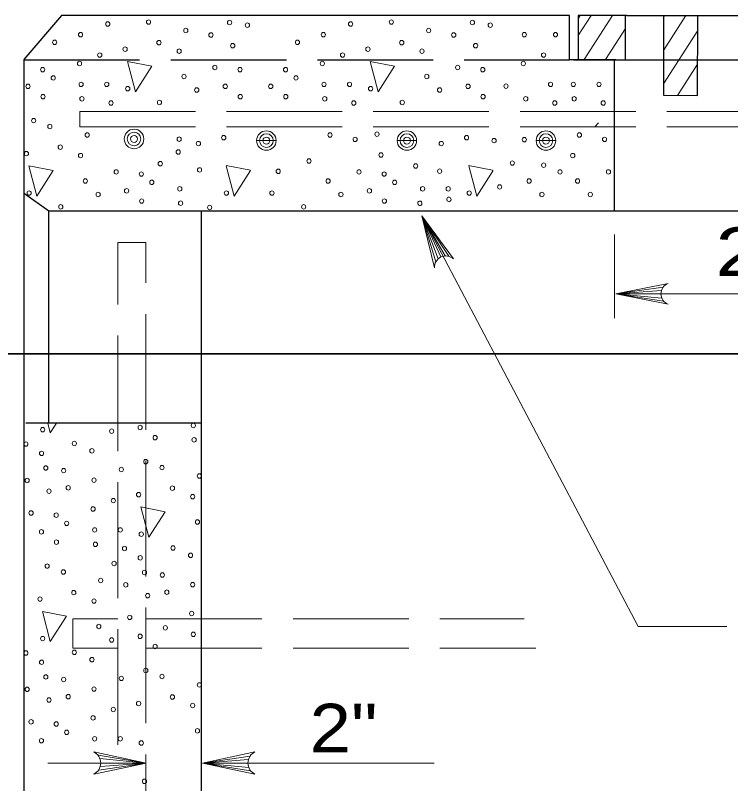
# Model space of a CAD drawing. Extents: x 1329.9 to 1363.9, y 715.5 to 737.5.
# Drawn here: x 1332.839 to 1335.139, y 731.635 to 734.106 of the extents above; entities that cross this region are included whole.
import ezdxf
from ezdxf.enums import TextEntityAlignment as Align

# ---------------------------------------------------------------- set-up
doc = ezdxf.new("R2010")
doc.units = 0
doc.header["$LTSCALE"] = 0.062
doc.linetypes.add('LONG_DASHED', pattern=[7.5, 6, -1.5])
doc.layers.add('1', color=7, linetype='Continuous', lineweight=13)

msp = doc.modelspace()

# ---------------------------------------------------------------- linework, layer by layer
at = {"layer": '1'}
for p, q in [((1334.64908, 734.04133), (1334.6905, 734.10575)), ((1334.64908, 734.095), (1334.656, 734.10575)), ((1334.66808, 733.96333), (1334.75958, 734.10575)), ((1334.9235, 733.99275), (1334.99592, 734.1055)), ((1334.92358, 734.10033), (1334.92708, 734.10567)), ((1335.03358, 734.10533), (1334.92367, 734.10575)), ((1334.73708, 733.96333), (1334.80158, 734.06383)), ((1334.92342, 733.88508), (1335.0335, 734.05658)), ((1334.96892, 733.84858), (1335.03333, 733.94892)), ((1333.04633, 733.79608), (1333.04633, 733.74733)), ((1333.04633, 733.79608), (1333.106, 733.79608)), ((1333.04633, 733.74733), (1333.108, 733.74733)), ((1334.70242, 733.74733), (1334.71467, 733.76033)), ((1332.88267, 733.62175), (1332.90833, 733.52442)), ((1333.595, 733.60817), (1333.51708, 733.62333)), ((1334.37408, 733.60817), (1334.29617, 733.62333)), ((1334.208, 733.32883), (1334.14617, 733.46058)), ((1334.2215, 733.33217), (1334.14617, 733.46058)), ((1334.23292, 733.33108), (1334.14617, 733.46058)), ((1334.19892, 733.32283), (1334.14617, 733.46058)), ((1334.19158, 733.31367), (1334.14617, 733.46058)), ((1334.76558, 733.40058), (1334.76558, 733.13242)), ((1334.92225, 733.2315), (1334.76992, 733.21025)), ((1334.91708, 733.221), (1334.76992, 733.21025)), ((1334.86892, 733.21025), (1334.76992, 733.21025)), ((1334.9155, 733.21025), (1334.76992, 733.21025)), ((1334.91817, 733.19658), (1334.76992, 733.21025)), ((1334.924, 733.18667), (1334.76992, 733.21025)), ((1333.1055, 731.7265), (1333.25958, 731.7015)), ((1333.11133, 731.716), (1333.25958, 731.7015)), ((1333.59392, 731.72408), (1333.44167, 731.7015)), ((1332.94333, 731.7015), (1333.25958, 731.7015)), ((1333.10733, 731.679), (1333.25958, 731.7015)), ((1333.11242, 731.69017), (1333.25958, 731.7015)), ((1333.114, 731.7015), (1333.25958, 731.7015)), ((1333.58875, 731.71292), (1333.44167, 731.7015)), ((1333.44167, 731.7015), (1334.18592, 731.7015)), ((1333.58725, 731.7015), (1333.44167, 731.7015)), ((1333.58992, 731.68708), (1333.44167, 731.7015)), ((1333.59575, 731.67658), (1333.44167, 731.7015))]:
    msp.add_line(p, q, dxfattribs=at)
at = {"layer": '1', "lineweight": 25}
for p, q in [((1334.80158, 733.96325), (1334.80158, 734.10575)), ((1334.80542, 734.10575), (1336.53992, 734.10575)), ((1332.86692, 733.96325), (1332.86692, 733.5425)), ((1334.76558, 733.47708), (1334.76558, 733.96325)), ((1334.80125, 733.96325), (1336.54408, 733.96325)), ((1332.86692, 733.5425), (1332.86692, 732.80092)), ((1332.86858, 733.53275), (1332.94725, 733.47708)), ((1332.94725, 732.79425), (1332.94725, 733.47708)), ((1332.94725, 733.47708), (1334.76992, 733.47708)), ((1333.43842, 729.84383), (1333.43842, 733.47708)), ((1334.76992, 733.47708), (1336.57183, 733.47708)), ((1332.86692, 732.80092), (1332.86692, 729.46942)), ((1333.43842, 732.79425), (1332.87258, 732.79425))]:
    msp.add_line(p, q, dxfattribs=at)
at = {"layer": '1', "linetype": 'LONG_DASHED', "lineweight": 25}
msp.add_line((1332.86692, 733.96325), (1334.62167, 733.96325), dxfattribs=at)
at = {"layer": '1', "linetype": 'LONG_DASHED'}
for p, q in [((1333.04633, 733.79608), (1338.30508, 733.79608)), ((1333.04633, 733.74733), (1338.30508, 733.74733)), ((1333.61533, 733.70317), (1333.678, 733.70317)), ((1334.06717, 733.70317), (1334.12975, 733.70317)), ((1334.06717, 733.70317), (1334.12975, 733.70317)), ((1334.51433, 733.70317), (1334.57692, 733.70317)), ((1334.51433, 733.70317), (1334.57692, 733.70317)), ((1334.51433, 733.70317), (1334.57692, 733.70317)), ((1333.16925, 733.37567), (1333.259, 733.37567)), ((1333.16925, 731.76017), (1333.16925, 733.37567)), ((1333.02425, 732.1655), (1333.02425, 732.07058)), ((1333.02425, 732.1655), (1333.16917, 732.1655)), ((1333.26033, 732.1655), (1334.47525, 732.1655)), ((1333.02425, 732.07058), (1333.16917, 732.07058)), ((1333.26033, 732.07058), (1334.51267, 732.07058))]:
    msp.add_line(p, q, dxfattribs=at)
at = {"layer": '1', "lineweight": 25}
for points in [[(1334.76992, 733.96325), (1334.62167, 733.96325), (1334.62167, 734.10575), (1332.98725, 734.10575), (1332.8665, 733.96333)], [(1334.80542, 734.10575), (1334.64908, 734.10575), (1334.64908, 733.96325)], [(1334.92367, 734.10575), (1334.92325, 733.84867), (1335.03325, 733.84825), (1335.03358, 734.10533)], [(1334.63383, 733.96325), (1334.76992, 733.96325), (1334.80125, 733.96325)]]:
    msp.add_lwpolyline(points, dxfattribs=at)
at = {"layer": '1'}
for points in [[(1333.19992, 733.9575), (1333.22558, 733.86025), (1333.27775, 733.94242)], [(1333.98075, 733.9575), (1334.00642, 733.86025), (1334.05858, 733.94242)], [(1333.24333, 732.525), (1333.269, 732.42758), (1333.32117, 732.50975)], [(1332.92617, 732.18917), (1332.95175, 732.09183), (1333.00408, 732.174)]]:
    msp.add_lwpolyline(points, close=True, dxfattribs=at)
for points in [[(1332.90833, 733.52442), (1332.96058, 733.6065), (1332.88267, 733.62175)], [(1333.51708, 733.62175), (1333.54275, 733.52442), (1333.595, 733.6065)], [(1334.29792, 733.62175), (1334.3235, 733.52442), (1334.37583, 733.6065)], [(1334.14617, 733.46058), (1334.84225, 732.14025), (1335.12683, 732.14025)], [(1334.24808, 733.32258), (1334.14617, 733.46058), (1334.18717, 733.294)], [(1334.93817, 733.17658), (1334.76992, 733.21025), (1334.93817, 733.24383)], [(1334.76992, 733.21025), (1335.88917, 733.21025), (1336.57183, 733.21025)], [(1332.94375, 732.79417), (1332.95175, 732.7635), (1332.97142, 732.79417)], [(1333.09133, 731.73717), (1333.25958, 731.7015), (1333.09133, 731.66592)], [(1333.60983, 731.66592), (1333.44167, 731.7015), (1333.60983, 731.73717)]]:
    msp.add_lwpolyline(points, dxfattribs=at)
at = {"layer": '1', "linetype": 'LONG_DASHED'}
msp.add_lwpolyline([(1333.259, 729.40917), (1333.259, 729.46942), (1333.259, 733.37567)], dxfattribs=at)
at = {"layer": '1', "lineweight": 35}
msp.add_lwpolyline([(1332.47342, 733.01742), (1338.878, 733.01742), (1338.878, 732.60617)], dxfattribs=at)
at = {"layer": '1'}
for centre, radius in [((1333.22102, 733.70835), 0.03133), ((1333.22102, 733.70835), 0.0219), ((1333.22102, 733.70835), 0.01122), ((1333.64666, 733.70316), 0.03133), ((1333.64666, 733.70316), 0.0219), ((1333.64666, 733.70316), 0.01122), ((1334.09846, 733.70316), 0.03133), ((1334.09846, 733.70316), 0.0219), ((1334.09846, 733.70316), 0.01122), ((1334.54563, 733.70316), 0.03133), ((1334.54563, 733.70316), 0.0219), ((1334.54563, 733.70316), 0.01122)]:
    msp.add_circle(centre, radius, dxfattribs=at)
for centre, start, end in [((1334.22336, 733.29598), 47.22812, 183.05425), ((1334.95175, 733.21026), 112.08782, 247.91395)]:
    msp.add_arc(centre, 0.03631, start, end, dxfattribs=at)
for centre, major_axis in [((1333.13658, 734.07782), (0, 0.00718)), ((1333.26763, 734.08415), (0, 0.00718)), ((1333.52832, 734.08263), (0, 0.00718)), ((1333.91738, 734.07782), (0, 0.00718)), ((1334.04844, 734.08415), (0, 0.00718)), ((1334.30912, 734.08263), (0, 0.00718)), ((1333.38753, 734.05694), (0, 0.00718)), ((1333.58568, 734.07441), (0, 0.00718)), ((1334.16834, 734.05694), (0, 0.00718)), ((1334.36648, 734.07441), (0, 0.00718)), ((1333.04892, 734.04357), (0, 0.00718)), ((1333.46831, 734.04273), (0, 0.00718)), ((1333.82973, 734.04357), (0, 0.00718)), ((1334.24912, 734.04273), (0, 0.00718)), ((1334.47608, 734.04357), (0, 0.00718)), ((1334.57631, 734.04357), (0, 0.00718)), ((1332.96582, 734.01916), (0, 0.00718)), ((1333.30099, 734.01793), (0, 0.00718)), ((1333.53852, 734.00825), (0, 0.00718)), ((1333.74662, 734.01916), (0, 0.00718)), ((1334.0818, 734.01793), (0, 0.00718)), ((1334.31933, 734.00825), (0, 0.00718)), ((1333.19225, 733.99706), (0, 0.00718)), ((1333.36612, 733.99073), (0, 0.00718)), ((1333.97305, 733.99706), (0, 0.00718)), ((1334.14693, 733.99073), (0, 0.00718)), ((1333.11083, 733.97803), (0, 0.00718)), ((1333.89163, 733.97803), (0, 0.00718)), ((1334.53799, 733.97803), (0, 0.00718)), ((1332.92733, 733.93118), (0, 0.00718)), ((1333.0458, 733.95082), (0, 0.00718)), ((1333.4809, 733.93818), (0, 0.00718)), ((1333.56173, 733.93118), (0, 0.00718)), ((1333.70813, 733.93118), (0, 0.00718)), ((1333.82661, 733.95082), (0, 0.00718)), ((1334.2617, 733.93818), (0, 0.00718)), ((1334.34253, 733.93118), (0, 0.00718)), ((1334.47296, 733.95082), (0, 0.00718)), ((1332.96101, 733.90459), (0, 0.00718)), ((1333.38156, 733.90913), (0, 0.00718)), ((1333.74181, 733.90459), (0, 0.00718)), ((1334.16236, 733.90913), (0, 0.00718)), ((1333.05093, 733.88372), (0, 0.00718)), ((1333.13319, 733.88372), (0, 0.00718)), ((1333.83174, 733.88372), (0, 0.00718)), ((1333.914, 733.88372), (0, 0.00718)), ((1334.56035, 733.88372), (0, 0.00718)), ((1334.63378, 733.88372), (0, 0.00718)), ((1334.71604, 733.88372), (0, 0.00718)), ((1332.87991, 733.87739), (0, 0.00718)), ((1333.20081, 733.87012), (0, 0.00718)), ((1333.42269, 733.86558), (0, 0.00718)), ((1333.51431, 733.87739), (0, 0.00718)), ((1333.66071, 733.87739), (0, 0.00718)), ((1333.98161, 733.87012), (0, 0.00718)), ((1334.20349, 733.86558), (0, 0.00718)), ((1334.29511, 733.87739), (0, 0.00718)), ((1334.41704, 733.87827), (0, 0.00718)), ((1332.92818, 733.84442), (0, 0.00718)), ((1333.05347, 733.83748), (0, 0.00718)), ((1333.56258, 733.84442), (0, 0.00718)), ((1333.70898, 733.84442), (0, 0.00718)), ((1333.83427, 733.83748), (0, 0.00718)), ((1334.34338, 733.84442), (0, 0.00718)), ((1334.48063, 733.83748), (0, 0.00718)), ((1334.63632, 733.83748), (0, 0.00718)), ((1333.14689, 733.82388), (0, 0.00718)), ((1333.30274, 733.82567), (0, 0.00718)), ((1333.92769, 733.82388), (0, 0.00718)), ((1334.08354, 733.82567), (0, 0.00718)), ((1334.57404, 733.82388), (0, 0.00718)), ((1334.72973, 733.82388), (0, 0.00718)), ((1332.8982, 733.76735), (0, 0.00718)), ((1332.95043, 733.74832), (0, 0.00718)), ((1333.07033, 733.72112), (0, 0.00718)), ((1333.36612, 733.70774), (0, 0.00718)), ((1333.50944, 733.71252), (0, 0.00718)), ((1333.85114, 733.72112), (0, 0.00718)), ((1333.93192, 733.70691), (0, 0.00718)), ((1334.00213, 733.72371), (0, 0.00718)), ((1334.29025, 733.71252), (0, 0.00718)), ((1334.65318, 733.72112), (0, 0.00718)), ((1334.73396, 733.70691), (0, 0.00718)), ((1333.42803, 733.69349), (0, 0.00718)), ((1334.20883, 733.69349), (0, 0.00718)), ((1334.37885, 733.70302), (0, 0.00718)), ((1334.47608, 733.70619), (0, 0.00718)), ((1332.87505, 733.66123), (0, 0.00718)), ((1332.98379, 733.68211), (0, 0.00718)), ((1333.363, 733.66629), (0, 0.00718)), ((1333.04892, 733.65491), (0, 0.00718)), ((1333.78359, 733.63728), (0, 0.00718)), ((1334.01511, 733.65685), (0, 0.00718)), ((1334.63177, 733.65491), (0, 0.00718)), ((1333.30523, 733.62885), (0, 0.00718)), ((1333.4316, 733.6088), (0, 0.00718)), ((1334.12672, 733.62141), (0, 0.00718)), ((1334.4374, 733.63082), (0, 0.00718)), ((1334.53833, 733.62404), (0, 0.00718)), ((1333.1637, 733.60235), (0, 0.00718)), ((1333.24453, 733.59536), (0, 0.00718)), ((1333.68465, 733.60433), (0, 0.00718)), ((1333.9445, 733.60235), (0, 0.00718)), ((1334.02533, 733.59536), (0, 0.00718)), ((1334.20393, 733.60481), (0, 0.00718)), ((1334.59085, 733.60235), (0, 0.00718)), ((1334.74654, 733.60235), (0, 0.00718)), ((1333.06436, 733.5733), (0, 0.00718)), ((1333.27821, 733.56877), (0, 0.00718)), ((1333.84517, 733.5733), (0, 0.00718)), ((1334.05901, 733.56877), (0, 0.00718)), ((1334.49152, 733.5733), (0, 0.00718)), ((1334.64721, 733.5733), (0, 0.00718)), ((1332.88361, 733.53429), (0, 0.00718)), ((1333.19711, 733.54157), (0, 0.00718)), ((1333.36813, 733.54789), (0, 0.00718)), ((1333.51801, 733.53429), (0, 0.00718)), ((1333.66441, 733.53429), (0, 0.00718)), ((1333.97791, 733.54157), (0, 0.00718)), ((1334.14894, 733.54789), (0, 0.00718)), ((1334.2312, 733.54789), (0, 0.00718)), ((1334.29881, 733.53429), (0, 0.00718)), ((1334.39679, 733.55411), (0, 0.00718)), ((1333.10549, 733.52976), (0, 0.00718)), ((1333.8863, 733.52976), (0, 0.00718)), ((1334.23351, 733.51418), (-0.00198, 0.0069)), ((1334.53265, 733.52976), (0, 0.00718)), ((1334.68834, 733.52976), (0, 0.00718)), ((1332.98554, 733.48985), (0, 0.00718)), ((1333.24538, 733.5086), (0, 0.00718)), ((1333.37067, 733.50166), (0, 0.00718)), ((1333.46408, 733.48806), (0, 0.00718)), ((1333.76634, 733.48985), (0, 0.00718)), ((1334.02618, 733.5086), (0, 0.00718)), ((1334.13996, 733.50154), (-0.00198, 0.0069)), ((1332.92706, 732.77338), (0, 0.00718)), ((1333.14894, 732.76884), (0, 0.00718)), ((1333.24056, 732.78065), (0, 0.00718)), ((1333.41158, 732.78698), (0, 0.00718)), ((1333.28882, 732.74768), (0, 0.00718)), ((1332.87314, 732.72714), (0, 0.00718)), ((1333.02899, 732.72893), (0, 0.00718)), ((1333.41412, 732.74074), (0, 0.00718)), ((1332.92362, 732.6972), (0, 0.00718)), ((1333.0855, 732.70537), (0, 0.00718)), ((1333.25885, 732.67061), (0, 0.00718)), ((1332.93737, 732.65007), (0, 0.00718)), ((1333.18003, 732.64526), (0, 0.00718)), ((1333.31108, 732.65158), (0, 0.00718)), ((1332.99473, 732.64184), (0, 0.00718)), ((1333.43098, 732.62438), (0, 0.00718)), ((1332.87736, 732.61017), (0, 0.00718)), ((1333.09237, 732.61101), (0, 0.00718)), ((1332.94757, 732.57569), (0, 0.00718)), ((1333.00927, 732.5866), (0, 0.00718)), ((1333.34444, 732.58537), (0, 0.00718)), ((1333.23569, 732.56449), (0, 0.00718)), ((1333.40957, 732.55817), (0, 0.00718)), ((1333.15428, 732.54546), (0, 0.00718)), ((1332.88995, 732.50561), (0, 0.00718)), ((1332.97078, 732.49862), (0, 0.00718)), ((1333.08925, 732.51826), (0, 0.00718)), ((1333.00446, 732.47203), (0, 0.00718)), ((1333.42501, 732.47656), (0, 0.00718)), ((1333.09438, 732.45115), (0, 0.00718)), ((1333.17664, 732.45115), (0, 0.00718)), ((1332.92336, 732.44483), (0, 0.00718)), ((1333.24426, 732.43755), (0, 0.00718)), ((1332.97163, 732.41186), (0, 0.00718)), ((1333.09692, 732.40492), (0, 0.00718)), ((1333.19033, 732.39132), (0, 0.00718)), ((1333.34619, 732.39311), (0, 0.00718)), ((1333.24082, 732.36138), (0, 0.00718)), ((1333.4027, 732.36955), (0, 0.00718)), ((1332.94165, 732.33479), (0, 0.00718)), ((1333.15687, 732.34324), (0, 0.00718)), ((1332.99388, 732.31576), (0, 0.00718)), ((1333.25457, 732.31425), (0, 0.00718)), ((1333.31193, 732.30602), (0, 0.00718)), ((1333.11378, 732.28856), (0, 0.00718)), ((1333.19456, 732.27434), (0, 0.00718)), ((1333.40957, 732.27518), (0, 0.00718)), ((1333.02724, 732.24955), (0, 0.00718)), ((1333.32647, 732.25078), (0, 0.00718)), ((1332.91849, 732.22867), (0, 0.00718)), ((1333.26477, 732.23986), (0, 0.00718)), ((1333.09237, 732.22235), (0, 0.00718)), ((1333.40645, 732.18244), (0, 0.00718)), ((1333.20715, 732.16979), (0, 0.00718)), ((1333.10781, 732.14074), (0, 0.00718)), ((1333.32165, 732.13621), (0, 0.00718)), ((1332.92706, 732.10173), (0, 0.00718)), ((1333.24056, 732.10901), (0, 0.00718)), ((1333.41158, 732.11533), (0, 0.00718)), ((1333.14894, 732.0972), (0, 0.00718)), ((1332.87314, 732.0555), (0, 0.00718)), ((1333.02899, 732.05729), (0, 0.00718)), ((1333.28882, 732.07604), (0, 0.00718)), ((1333.0855, 732.03373), (0, 0.00718)), ((1332.92362, 732.02555), (0, 0.00718)), ((1332.93737, 731.97843), (0, 0.00718)), ((1333.25885, 731.99897), (0, 0.00718)), ((1333.31108, 731.97994), (0, 0.00718)), ((1332.99473, 731.9702), (0, 0.00718)), ((1333.18003, 731.97361), (0, 0.00718)), ((1332.87736, 731.93852), (0, 0.00718)), ((1333.09237, 731.93936), (0, 0.00718)), ((1333.43098, 731.95274), (0, 0.00718)), ((1332.94757, 731.90404), (0, 0.00718)), ((1333.00927, 731.91496), (0, 0.00718)), ((1333.34444, 731.91372), (0, 0.00718)), ((1333.23569, 731.89285), (0, 0.00718)), ((1333.40957, 731.88652), (0, 0.00718)), ((1333.15428, 731.87382), (0, 0.00718)), ((1332.88995, 731.83397), (0, 0.00718)), ((1333.08925, 731.84662), (0, 0.00718)), ((1332.97078, 731.82697), (0, 0.00718)), ((1333.42501, 731.80492), (0, 0.00718)), ((1333.00446, 731.80038), (0, 0.00718)), ((1332.92336, 731.77318), (0, 0.00718)), ((1333.09438, 731.77951), (0, 0.00718)), ((1333.17664, 731.77951), (0, 0.00718)), ((1333.24426, 731.76591), (0, 0.00718)), ((1333.25457, 731.6426), (0, 0.00718))]:
    msp.add_ellipse(centre, major_axis=major_axis, ratio=0.944544, dxfattribs=at)
for centre, major_axis in [((1333.07772, 731.70153), (0, -0.03844)), ((1333.62352, 731.70154), (0, 0.03844))]:
    msp.add_ellipse(centre, major_axis=major_axis, ratio=0.944544, start_param=0.3855052, end_param=2.7561184, dxfattribs=at)

# ---------------------------------------------------------------- texts
for s, width, p in [('2\'-0" [600]', 1.3, (1335.69967, 733.26808)), ('2"', 1.15, (1333.89471, 731.73608))]:
    msp.add_text(s, height=0.156, dxfattribs=dict(at, width=width)).set_placement(p, align=Align.CENTER)

doc.saveas('drawing.dxf')
